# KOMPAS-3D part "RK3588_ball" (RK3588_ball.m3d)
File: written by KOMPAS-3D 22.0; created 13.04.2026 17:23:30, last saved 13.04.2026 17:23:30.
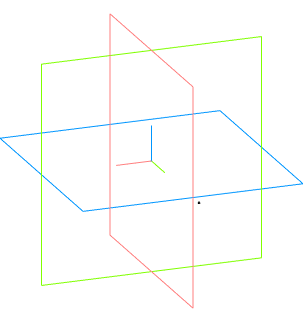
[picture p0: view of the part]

Document properties: Автор: Andrey; Полное имя файла: C:\Users\User1\Documents\RK3588_ball.m3d

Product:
- Part/product: RK3588_ball

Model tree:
1. Операция без истории:1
